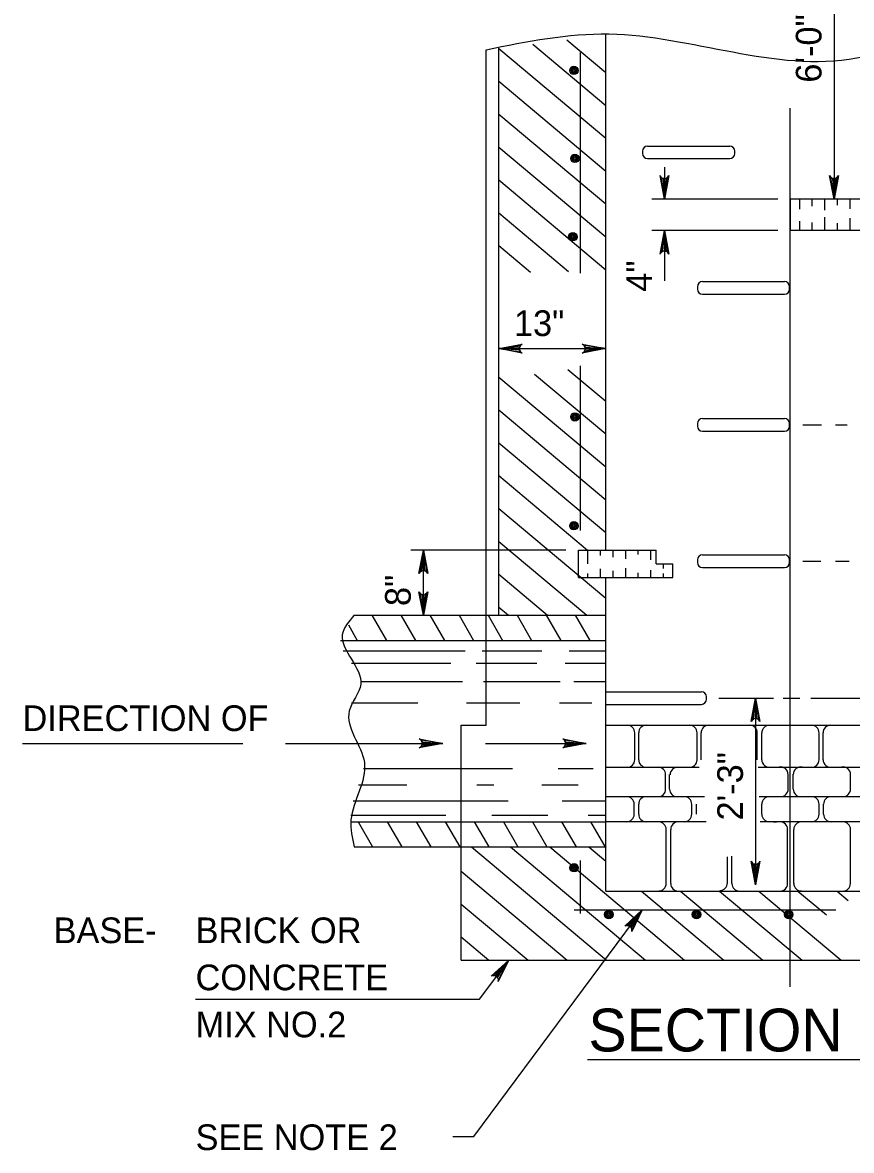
# Model space of a CAD drawing. Extents: x 0.2 to 7.1, y 1.2 to 11.2.
# Drawn here: x 0.162 to 2.099, y 2.91 to 5.546 of the extents above; entities that cross this region are included whole.
import ezdxf

# ---------------------------------------------------------------- set-up
doc = ezdxf.new("R2010")
doc.units = 0
for name, color, linetype in [('DETL-DIMS', 7, 'Continuous'), ('DETL-LINE', 7, 'Continuous'), ('DETL-NOTE', 7, 'Continuous'), ('DETL-PATT', 7, 'Continuous'), ('DETL-TITL', 7, 'Continuous')]:
    doc.layers.add(name, color=color, linetype=linetype)

msp = doc.modelspace()

# ---------------------------------------------------------------- linework, layer by layer
at = {"layer": 'DETL-DIMS'}
for p, q in [((2.0587, 5.879), (2.0587, 5.1333)), ((1.9564, 3.2924), (1.9564, 5.346)), ((1.6623, 5.2079), (1.6623, 5.1333)), ((1.927, 5.1333), (1.6329, 5.1333)), ((1.927, 5.0598), (1.6329, 5.0598)), ((1.6623, 5.0598), (1.6623, 4.9421)), ((1.275, 4.7839), (1.525, 4.7839)), ((1.9858, 4.6055), (2.0295, 4.6055)), ((2.0623, 4.6055), (2.0892, 4.6055)), ((1.4319, 4.313), (1.0691, 4.313)), ((1.0986, 4.1611), (1.0986, 4.313)), ((1.9858, 4.2871), (2.028, 4.2871)), ((2.0623, 4.2871), (2.0937, 4.2871)), ((1.7897, 3.9672), (1.9175, 3.9672)), ((1.8751, 3.9672), (1.8751, 3.5312)), ((1.9399, 3.9672), (1.9787, 3.9672)), ((2.0041, 3.9672), (2.2211, 3.9672)), ((0.1617, 3.8615), (0.6763, 3.8615)), ((0.7763, 3.8615), (1.1439, 3.8615)), ((1.2439, 3.8615), (1.4791, 3.8615)), ((1.2167, 2.9432), (1.6103, 3.4723)), ((1.2302, 3.2636), (1.2983, 3.3551)), ((0.5662, 3.2636), (1.2302, 3.2636)), ((1.1672, 2.9432), (1.2167, 2.9432))]:
    msp.add_line(p, q, dxfattribs=at)
for points in [[(1.6623, 5.1333), (1.652, 5.1881), (1.6549, 5.1839), (1.6586, 5.1817), (1.6623, 5.1811), (1.666, 5.1817), (1.6696, 5.1839), (1.6726, 5.1881), (1.6623, 5.1333), (1.6696, 5.1839), (1.666, 5.1817), (1.6623, 5.1333), (1.6623, 5.1811), (1.6586, 5.1817), (1.6623, 5.1333), (1.6549, 5.1839)], [(2.0587, 5.1333), (2.0484, 5.1881), (2.0514, 5.1839), (2.055, 5.1817), (2.0587, 5.1811), (2.0624, 5.1817), (2.0661, 5.1839), (2.069, 5.1881), (2.0587, 5.1333), (2.0661, 5.1839), (2.0624, 5.1817), (2.0587, 5.1333), (2.0587, 5.1811), (2.055, 5.1817), (2.0587, 5.1333), (2.0514, 5.1839)], [(1.6623, 5.0598), (1.6726, 5.0049), (1.6696, 5.0092), (1.666, 5.0113), (1.6623, 5.012), (1.6586, 5.0113), (1.6549, 5.0092), (1.652, 5.0049), (1.6623, 5.0598), (1.6549, 5.0092), (1.6586, 5.0113), (1.6623, 5.0598), (1.6623, 5.012), (1.666, 5.0113), (1.6623, 5.0598), (1.6696, 5.0092)], [(1.275, 4.7839), (1.3299, 4.7942), (1.3256, 4.7913), (1.3234, 4.7876), (1.3228, 4.7839), (1.3234, 4.7803), (1.3256, 4.7766), (1.3299, 4.7737), (1.275, 4.7839), (1.3256, 4.7766), (1.3234, 4.7803), (1.275, 4.7839), (1.3228, 4.7839), (1.3234, 4.7876), (1.275, 4.7839), (1.3256, 4.7913)], [(1.525, 4.7839), (1.4702, 4.7737), (1.4744, 4.7766), (1.4766, 4.7803), (1.4772, 4.7839), (1.4766, 4.7876), (1.4744, 4.7913), (1.4702, 4.7942), (1.525, 4.7839), (1.4744, 4.7913), (1.4766, 4.7876), (1.525, 4.7839), (1.4772, 4.7839), (1.4766, 4.7803), (1.525, 4.7839), (1.4744, 4.7766)], [(1.0986, 4.313), (1.1088, 4.2582), (1.1059, 4.2624), (1.1022, 4.2646), (1.0986, 4.2652), (1.0949, 4.2646), (1.0912, 4.2624), (1.0883, 4.2582), (1.0986, 4.313), (1.0912, 4.2624), (1.0949, 4.2646), (1.0986, 4.313), (1.0986, 4.2652), (1.1022, 4.2646), (1.0986, 4.313), (1.1059, 4.2624)], [(1.0986, 4.1611), (1.0883, 4.2159), (1.0912, 4.2117), (1.0949, 4.2095), (1.0986, 4.2089), (1.1022, 4.2095), (1.1059, 4.2117), (1.1088, 4.2159), (1.0986, 4.1611), (1.1059, 4.2117), (1.1022, 4.2095), (1.0986, 4.1611), (1.0986, 4.2089), (1.0949, 4.2095), (1.0986, 4.1611), (1.0912, 4.2117)], [(1.8751, 3.9672), (1.8854, 3.9124), (1.8825, 3.9166), (1.8788, 3.9188), (1.8751, 3.9194), (1.8715, 3.9188), (1.8678, 3.9166), (1.8649, 3.9124), (1.8751, 3.9672), (1.8678, 3.9166), (1.8715, 3.9188), (1.8751, 3.9672), (1.8751, 3.9194), (1.8788, 3.9188), (1.8751, 3.9672), (1.8825, 3.9166)], [(1.1439, 3.8615), (1.0891, 3.8513), (1.0933, 3.8542), (1.0955, 3.8579), (1.0961, 3.8615), (1.0955, 3.8652), (1.0933, 3.8689), (1.0891, 3.8718), (1.1439, 3.8615), (1.0933, 3.8689), (1.0955, 3.8652), (1.1439, 3.8615), (1.0961, 3.8615), (1.0955, 3.8579), (1.1439, 3.8615), (1.0933, 3.8542)], [(1.4791, 3.8615), (1.4243, 3.8513), (1.4285, 3.8542), (1.4307, 3.8579), (1.4313, 3.8615), (1.4307, 3.8652), (1.4285, 3.8689), (1.4243, 3.8718), (1.4791, 3.8615), (1.4285, 3.8689), (1.4307, 3.8652), (1.4791, 3.8615), (1.4313, 3.8615), (1.4307, 3.8579), (1.4791, 3.8615), (1.4285, 3.8542)], [(1.8751, 3.5312), (1.8649, 3.586), (1.8678, 3.5818), (1.8715, 3.5796), (1.8751, 3.579), (1.8788, 3.5796), (1.8825, 3.5818), (1.8854, 3.586), (1.8751, 3.5312), (1.8825, 3.5818), (1.8788, 3.5796), (1.8751, 3.5312), (1.8751, 3.579), (1.8715, 3.5796), (1.8751, 3.5312), (1.8678, 3.5818)], [(1.6103, 3.4723), (1.5858, 3.4222), (1.586, 3.4274), (1.5843, 3.4313), (1.5818, 3.434), (1.5784, 3.4357), (1.5742, 3.4361), (1.5693, 3.4345), (1.6103, 3.4723), (1.5742, 3.4361), (1.5784, 3.4357), (1.6103, 3.4723), (1.5818, 3.434), (1.5843, 3.4313), (1.6103, 3.4723), (1.586, 3.4274)], [(1.2983, 3.3551), (1.2738, 3.305), (1.274, 3.3101), (1.2723, 3.3141), (1.2697, 3.3168), (1.2664, 3.3185), (1.2622, 3.3189), (1.2573, 3.3173), (1.2983, 3.3551), (1.2622, 3.3189), (1.2664, 3.3185), (1.2983, 3.3551), (1.2697, 3.3168), (1.2723, 3.3141), (1.2983, 3.3551), (1.274, 3.3101)]]:
    msp.add_lwpolyline(points, dxfattribs=at)
at = {"layer": 'DETL-LINE'}
for p, q in [((1.525, 4.313), (1.525, 5.5179)), ((1.2456, 4.1611), (1.2456, 5.4822)), ((1.275, 4.1611), (1.275, 5.4859)), ((1.4662, 4.96), (1.4662, 5.4761)), ((1.6112, 5.2456), (1.6112, 5.2397)), ((1.6229, 5.2573), (1.8147, 5.2573)), ((1.8265, 5.2397), (1.8265, 5.2456)), ((1.6229, 5.2279), (1.8147, 5.2279)), ((2.4515, 5.1333), (1.9564, 5.1333)), ((1.9564, 5.1333), (1.9564, 5.0598)), ((2.4515, 5.0598), (1.9564, 5.0598)), ((1.7395, 4.9288), (1.7395, 4.9229)), ((1.7512, 4.9406), (1.943, 4.9406)), ((1.9548, 4.9229), (1.9548, 4.9288)), ((1.7512, 4.9112), (1.943, 4.9112)), ((1.4662, 4.3588), (1.4662, 4.7441)), ((1.7512, 4.6204), (1.943, 4.6204)), ((1.7395, 4.6087), (1.7395, 4.6028)), ((1.7512, 4.591), (1.943, 4.591)), ((1.9548, 4.6028), (1.9548, 4.6087)), ((1.4613, 4.2493), (1.4613, 4.313)), ((1.4613, 4.313), (1.6427, 4.313)), ((1.6427, 4.2812), (1.6427, 4.313)), ((1.7512, 4.302), (1.943, 4.302)), ((1.6427, 4.2812), (1.6819, 4.2812)), ((1.6819, 4.2493), (1.6819, 4.2812)), ((1.7395, 4.2902), (1.7395, 4.2843)), ((1.7512, 4.2726), (1.943, 4.2726)), ((1.9548, 4.2843), (1.9548, 4.2902)), ((1.4613, 4.2493), (1.6819, 4.2493)), ((1.525, 3.5165), (1.525, 4.2493)), ((0.9368, 4.1611), (1.525, 4.1611)), ((1.2456, 3.9037), (1.2456, 4.1611)), ((0.9051, 4.1022), (1.525, 4.1022)), ((1.525, 3.9822), (1.7486, 3.9822)), ((1.7603, 3.9645), (1.7603, 3.9704)), ((1.525, 3.9527), (1.7486, 3.9527)), ((1.1868, 3.9037), (1.2456, 3.9037)), ((1.1868, 3.6194), (1.1868, 3.9037)), ((1.525, 3.9037), (2.3878, 3.9037)), ((1.5928, 3.8233), (1.5928, 3.8861)), ((1.602, 3.8233), (1.602, 3.8861)), ((1.7386, 3.8233), (1.7386, 3.8861)), ((1.7478, 3.8233), (1.7478, 3.8861)), ((1.8792, 3.8233), (1.8792, 3.8861)), ((1.8897, 3.8233), (1.8897, 3.8861)), ((2.0237, 3.8233), (2.0237, 3.8861)), ((2.0329, 3.8233), (2.0329, 3.8861)), ((1.525, 3.8057), (1.743, 3.8057)), ((1.6293, 3.8057), (1.6365, 3.8057)), ((1.8815, 3.8057), (2.3548, 3.8057)), ((1.665, 3.7547), (1.665, 3.788)), ((1.6742, 3.7547), (1.6742, 3.7888)), ((1.9515, 3.7547), (1.9515, 3.7888)), ((1.9633, 3.7547), (1.9633, 3.7895)), ((2.0973, 3.7547), (2.0973, 3.7888)), ((1.525, 3.7371), (1.7557, 3.7371)), ((1.5915, 3.6959), (1.5915, 3.7194)), ((1.602, 3.6959), (1.602, 3.7194)), ((1.6293, 3.7371), (1.6365, 3.7371)), ((1.7012, 3.7371), (1.7084, 3.7371)), ((1.726, 3.6959), (1.726, 3.7194)), ((1.7371, 3.6959), (1.7371, 3.7194)), ((1.8836, 3.7371), (2.3878, 3.7371)), ((1.8897, 3.6959), (1.8897, 3.7194)), ((1.9168, 3.7371), (1.924, 3.7371)), ((1.9887, 3.7371), (1.9959, 3.7371)), ((2.0237, 3.6959), (2.0237, 3.7194)), ((2.0342, 3.6959), (2.0342, 3.7194)), ((2.0606, 3.7371), (2.0678, 3.7371)), ((0.93, 3.6782), (1.525, 3.6782)), ((1.7599, 3.6782), (1.525, 3.6782)), ((2.3878, 3.6782), (1.8857, 3.6782)), ((1.9168, 3.6782), (1.924, 3.6782)), ((1.6664, 3.5342), (1.6664, 3.6606)), ((1.6769, 3.534), (1.6769, 3.6606)), ((1.9501, 3.534), (1.9501, 3.6606)), ((1.9646, 3.5342), (1.9646, 3.6606)), ((2.0973, 3.5332), (2.0973, 3.6606)), ((0.9368, 3.6194), (1.525, 3.6194)), ((1.1868, 3.3547), (1.1868, 3.6194)), ((1.4662, 3.4641), (1.4662, 3.5879)), ((1.8096, 3.5353), (1.8096, 3.5965)), ((1.8201, 3.534), (1.8201, 3.5976)), ((1.525, 3.5165), (2.3878, 3.5165)), ((1.4511, 3.4723), (2.0627, 3.4723)), ((1.1868, 3.3547), (2.726, 3.3547))]:
    msp.add_line(p, q, dxfattribs=at)
for centre, radius in [((1.4506, 5.434), 0.0098), ((1.4506, 5.434), 0.00735), ((1.4506, 5.434), 0.0049), ((1.4506, 5.434), 0.00245), ((1.453, 5.2285), 0.0098), ((1.453, 5.2285), 0.00735), ((1.453, 5.2285), 0.0049), ((1.453, 5.2285), 0.00245), ((1.4481, 5.0453), 0.0098), ((1.4481, 5.0453), 0.00735), ((1.4481, 5.0453), 0.0049), ((1.4481, 5.0453), 0.00245), ((1.453, 4.6244), 0.0098), ((1.453, 4.6244), 0.00735), ((1.453, 4.6244), 0.0049), ((1.453, 4.6244), 0.00245), ((1.4506, 4.37), 0.0098), ((1.4506, 4.37), 0.00735), ((1.4506, 4.37), 0.0049), ((1.4506, 4.37), 0.00245), ((1.4511, 3.5708), 0.0098), ((1.4511, 3.5708), 0.00735), ((1.4511, 3.5708), 0.0049), ((1.4511, 3.5708), 0.00245), ((1.5322, 3.4614), 0.0098), ((1.5322, 3.4614), 0.00735), ((1.5322, 3.4614), 0.0049), ((1.5322, 3.4614), 0.00245), ((1.7371, 3.4614), 0.0098), ((1.7371, 3.4614), 0.00735), ((1.7371, 3.4614), 0.0049), ((1.7371, 3.4614), 0.00245), ((1.9526, 3.4614), 0.0098), ((1.9526, 3.4614), 0.00735), ((1.9526, 3.4614), 0.0049), ((1.9526, 3.4614), 0.00245)]:
    msp.add_circle(centre, radius, dxfattribs=at)
for centre, radius, start, end in [((1.6229, 5.2456), 0.0118, 90, 180), ((1.8147, 5.2456), 0.0118, 0, 90), ((1.6229, 5.2397), 0.0118, 180, 270), ((1.8147, 5.2397), 0.0118, 270, 0), ((1.7512, 4.9288), 0.0118, 90, 180), ((1.943, 4.9288), 0.0118, 0, 90), ((1.7512, 4.9229), 0.0118, 180, 270), ((1.943, 4.9229), 0.0118, 270, 0), ((1.7512, 4.6087), 0.0118, 90, 180), ((1.943, 4.6087), 0.0118, 0, 90), ((1.7512, 4.6028), 0.0118, 180, 270), ((1.943, 4.6028), 0.0118, 270, 0), ((1.7512, 4.2902), 0.0118, 90, 180), ((1.943, 4.2902), 0.0118, 0, 90), ((1.7512, 4.2843), 0.0118, 180, 270), ((1.943, 4.2843), 0.0118, 270, 0), ((1.7486, 3.9704), 0.0118, 0, 90), ((1.7486, 3.9645), 0.0118, 270, 0), ((1.5751, 3.8861), 0.0176, 0, 90), ((1.6196, 3.8861), 0.0176, 90, 180), ((1.721, 3.8861), 0.0176, 0, 90), ((1.7655, 3.8861), 0.0176, 90, 180), ((1.8616, 3.8861), 0.0176, 0, 90), ((1.9074, 3.8861), 0.0176, 90, 180), ((2.0061, 3.8861), 0.0176, 0, 90), ((2.0506, 3.8861), 0.0176, 90, 180), ((1.5751, 3.8233), 0.0176, 270, 0), ((1.6196, 3.8233), 0.0176, 180, 270), ((1.721, 3.8233), 0.0176, 258.2538, 0), ((1.9074, 3.8233), 0.0176, 180, 281.7563), ((2.0061, 3.8233), 0.0176, 270, 0), ((2.0506, 3.8233), 0.0176, 180, 281.7563), ((1.6474, 3.788), 0.0176, 0, 90), ((1.693, 3.7881), 0.0176, 78.2538, 180), ((1.9338, 3.7888), 0.0176, 0, 101.7563), ((1.9809, 3.7888), 0.0176, 78.2538, 180), ((2.0796, 3.7888), 0.0176, 0, 101.7563), ((1.6474, 3.7547), 0.0176, 270, 0), ((1.6919, 3.7547), 0.0176, 180, 270), ((1.9338, 3.7547), 0.0176, 270, 0), ((1.9809, 3.7547), 0.0176, 180, 270), ((2.0796, 3.7547), 0.0176, 270, 0), ((1.5738, 3.7194), 0.0176, 0, 90), ((1.6196, 3.7194), 0.0176, 90, 180), ((1.7084, 3.7194), 0.0176, 0, 90), ((1.9074, 3.7194), 0.0176, 90, 180), ((2.0061, 3.7194), 0.0176, 0, 90), ((2.0519, 3.7194), 0.0176, 90, 180), ((1.5738, 3.6959), 0.0176, 270, 0), ((1.6196, 3.6959), 0.0176, 180, 270), ((1.7084, 3.6959), 0.0176, 270, 0), ((1.9074, 3.6959), 0.0176, 180, 270), ((2.0061, 3.6961), 0.0176, 270, 0), ((2.0519, 3.6959), 0.0176, 180, 270), ((1.6487, 3.6606), 0.0176, 0, 90), ((1.6945, 3.6606), 0.0176, 90, 180), ((1.9325, 3.6606), 0.0176, 0, 90), ((1.9822, 3.6606), 0.0176, 90, 180), ((2.0796, 3.6606), 0.0176, 0, 90), ((1.6487, 3.5342), 0.0176, 270, 0), ((1.6945, 3.534), 0.0176, 180, 270), ((1.7919, 3.5353), 0.0176, 270, 0), ((1.8377, 3.534), 0.0176, 180, 270), ((1.9325, 3.534), 0.0176, 270, 0), ((1.9822, 3.5342), 0.0176, 180, 270), ((2.0794, 3.534), 0.0176, 270, 0)]:
    msp.add_arc(centre, radius, start, end, dxfattribs=at)
for points in [[(2.6672, 5.4817), (2.5405, 5.4658), (2.386, 5.508), (2.112, 5.4623), (1.5326, 5.5185), (1.2456, 5.4817)], [(0.9368, 4.1611), (0.9092, 4.115), (0.9525, 3.9997), (0.9254, 3.9373), (0.9607, 3.8167), (0.9295, 3.6825), (0.9368, 3.6194)]]:
    msp.add_spline(points, degree=3, dxfattribs=at)
at = {"layer": 'DETL-PATT'}
for p, q in [((1.275, 5.4854), (1.525, 5.2756)), ((1.3543, 5.4957), (1.525, 5.3524)), ((1.4337, 5.5058), (1.525, 5.4292)), ((1.275, 5.4086), (1.525, 5.1988)), ((1.275, 5.3318), (1.525, 5.122)), ((1.275, 5.255), (1.525, 5.0452)), ((1.275, 5.1782), (1.525, 4.9684)), ((1.9777, 5.1333), (1.9777, 5.1098)), ((2.0071, 5.1333), (2.0071, 5.1166)), ((2.0365, 5.1333), (2.0365, 5.1078)), ((2.0659, 5.1333), (2.0659, 5.1195)), ((2.0953, 5.1333), (2.0953, 5.1107)), ((1.275, 5.1014), (1.4381, 4.9645)), ((2.0365, 5.0914), (2.0365, 5.0598)), ((2.0953, 5.0885), (2.0953, 5.0598)), ((1.9777, 5.0817), (1.9777, 5.0598)), ((2.0071, 5.0788), (2.0071, 5.0598)), ((2.0659, 5.0769), (2.0659, 5.0598)), ((1.275, 5.0246), (1.349, 4.9625)), ((1.3582, 4.7245), (1.525, 4.5845)), ((1.4367, 4.7354), (1.525, 4.6613)), ((1.275, 4.7175), (1.525, 4.5077)), ((1.275, 4.6407), (1.525, 4.4309)), ((1.275, 4.5639), (1.525, 4.3541)), ((1.275, 4.4871), (1.4825, 4.313)), ((1.275, 4.4103), (1.525, 4.2005)), ((1.275, 4.3335), (1.4806, 4.1611)), ((1.4825, 4.313), (1.4825, 4.2807)), ((1.5119, 4.313), (1.5119, 4.3003)), ((1.5413, 4.313), (1.5413, 4.2963)), ((1.5708, 4.313), (1.5708, 4.2928)), ((1.6002, 4.313), (1.6002, 4.3026)), ((1.6296, 4.313), (1.6296, 4.2905)), ((1.5708, 4.2709), (1.5708, 4.2493)), ((1.659, 4.2812), (1.659, 4.2703)), ((1.275, 4.2567), (1.389, 4.1611)), ((1.4825, 4.2581), (1.4825, 4.2493)), ((1.5119, 4.2691), (1.5119, 4.2493)), ((1.5413, 4.2651), (1.5413, 4.2493)), ((1.6002, 4.2599), (1.6002, 4.2493)), ((1.6296, 4.2662), (1.6296, 4.2493)), ((1.659, 4.2587), (1.659, 4.2493)), ((1.275, 4.18), (1.2975, 4.1611)), ((0.9233, 4.1386), (0.9443, 4.1022)), ((0.9782, 4.1611), (1.0122, 4.1022)), ((1.0462, 4.1611), (1.0801, 4.1022)), ((1.1141, 4.1611), (1.148, 4.1022)), ((1.182, 4.1611), (1.216, 4.1022)), ((1.2499, 4.1611), (1.2839, 4.1022)), ((1.3178, 4.1611), (1.3518, 4.1022)), ((1.3858, 4.1611), (1.4197, 4.1022)), ((1.4537, 4.1611), (1.4877, 4.1022)), ((0.9115, 4.0781), (1.1963, 4.0781)), ((1.2363, 4.0781), (1.3754, 4.0781)), ((1.4394, 4.0781), (1.525, 4.0781)), ((0.9304, 4.0493), (1.1627, 4.0493)), ((1.2219, 4.0493), (1.3642, 4.0493)), ((1.4298, 4.0493), (1.525, 4.0493)), ((0.9524, 4.0061), (1.1899, 4.0061)), ((1.2395, 4.0061), (1.4186, 4.0061)), ((1.4506, 4.0061), (1.525, 4.0061)), ((0.931, 3.9565), (1.0859, 3.9565)), ((1.1995, 3.9565), (1.3243, 3.9565)), ((1.417, 3.9565), (1.4922, 3.9565)), ((0.9589, 3.8028), (1.3067, 3.8028)), ((1.4138, 3.8028), (1.4954, 3.8028)), ((0.9474, 3.7644), (1.0603, 3.7644)), ((1.2235, 3.7644), (1.2635, 3.7644)), ((1.3754, 3.7644), (1.4602, 3.7644)), ((0.9346, 3.7276), (1.2971, 3.7276)), ((1.4234, 3.7276), (1.525, 3.7276)), ((0.929, 3.694), (1.1515, 3.694)), ((1.2587, 3.694), (1.3898, 3.694)), ((1.4842, 3.694), (1.525, 3.694)), ((0.9461, 3.6782), (0.9801, 3.6194)), ((1.0141, 3.6782), (1.048, 3.6194)), ((1.082, 3.6782), (1.116, 3.6194)), ((1.1499, 3.6782), (1.1839, 3.6194)), ((1.2178, 3.6782), (1.2518, 3.6194)), ((1.2858, 3.6782), (1.3197, 3.6194)), ((1.3537, 3.6782), (1.3876, 3.6194)), ((1.4216, 3.6782), (1.4556, 3.6194)), ((1.4895, 3.6782), (1.525, 3.6168)), ((1.211, 3.6194), (1.5264, 3.3547)), ((1.3025, 3.6194), (1.6179, 3.3547)), ((1.394, 3.6194), (1.7094, 3.3547)), ((1.4855, 3.6194), (1.525, 3.5862)), ((1.1868, 3.5629), (1.4349, 3.3547)), ((1.6082, 3.5165), (1.801, 3.3547)), ((1.6997, 3.5165), (1.8925, 3.3547)), ((1.7912, 3.5165), (1.984, 3.3547)), ((1.8827, 3.5165), (2.0755, 3.3547)), ((1.9742, 3.5165), (2.0407, 3.4607)), ((2.0657, 3.5165), (2.0917, 3.4947)), ((1.1868, 3.4861), (1.3434, 3.3547)), ((1.1868, 3.4093), (1.2519, 3.3547))]:
    msp.add_line(p, q, dxfattribs=at)
at = {"layer": 'DETL-TITL'}
msp.add_line((1.4821, 3.1231), (2.4917, 3.1231), dxfattribs=at)

# ---------------------------------------------------------------- texts
at = {"layer": 'DETL-NOTE'}
for s, p in [('6\'-0"', (2.0293, 5.4054)), ('4"', (1.6329, 4.9169)), ('8"', (1.0691, 4.1824)), ('2\'-3"', (1.8457, 3.6814))]:
    msp.add_text(s, height=0.06, rotation=90, dxfattribs=at).set_placement(p)
for s, p in [('13"', (1.3104, 4.8134)), ('DIRECTION OF', (0.1617, 3.8904)), ('BASE-', (0.2344, 3.3947)), ('BRICK OR ', (0.5662, 3.3947)), ('CONCRETE', (0.5662, 3.2847)), ('MIX NO.2', (0.5662, 3.1747)), ('SEE NOTE 2', (0.5662, 2.9112))]:
    msp.add_text(s, height=0.06, dxfattribs=at).set_placement(p)
at = {"layer": 'DETL-TITL'}
msp.add_text('SECTION B-B', height=0.1, dxfattribs=at).set_placement((1.4845, 3.1417))

doc.saveas('drawing.dxf')
